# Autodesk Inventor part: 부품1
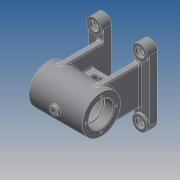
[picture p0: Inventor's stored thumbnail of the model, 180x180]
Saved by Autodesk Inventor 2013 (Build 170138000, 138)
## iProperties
Created: 2015-11
Part Number: 부품1
Material: 일반
Document SubType Name: Modeling
Designer: Administrator
Density: 1 g/cm^3
Author: Administrator
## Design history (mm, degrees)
sketch "스케치1"
  geometry: L1 (0, 0)-(70, 0); L2 (70, 0)-(70, 25); L3 (70, 25)-(0, 25); L4 (0, 25)-(0, 0); L5 (0, 16)-(12, 16); L6 (12, 16)-(12, 14); L7 (12, 14)-(14, 14); L8 (14, 14)-(14, 21); L9 (14, 21)-(56, 21); L10 (56, 21)-(56, 14); L11 (56, 14)-(58, 14); L12 (58, 14)-(58, 16); L13 (58, 16)-(70, 16)
  constraints: 26 end point, 8 parallel, 3 perpendicular, 2 collinear, 2 point on line, 1 horizontal
  dimensions: "d0" = 70 distance of L2.end L3.end; "d2" = 50 diameter of L3 L1; "d3" = 42 diameter of L9 L1; "d4" = 32 diameter of L13 L1; "d5" = 32 diameter of L5 L1; "d6" = 12 distance of L5.start L5.end; "d7" = 12 distance of L12.end L13.end; "d8" = 28 diameter of L7 L1; "d9" = 28 diameter of L11 L1; "d10" = 42 distance of L8.end L9.end
revolve "회전1" sketch "스케치1" stored, may be unused: angle "d11" = 90 deg
node "작업 평면1"
sketch "스케치2"
  geometry: L1 (-70, 25)-(-70, -25) reference; L2 (0, 25)-(0, -25) reference; L3 (-70, 25)-(-70, -25) reference; L4 (0, -25)-(-70, -25) reference; L5 (0, 25)-(-70, 25) reference; L6 (5, 40)-(5, -40); L7 (-35, 25)-(-35, -25); L8 (-5, 40)-(-5, -40); L9 (-15, 40)-(-15, -40); L10 (-55, 40)-(-55, -40); L11 (-75, 40)-(-75, -40); A1 r 10 centre (-5, 40) between (5, 40) and (-15, 40); A2 r 10 centre (-5, -40) between (-15, -40) and (5, -40); A3 r 10 centre (-65, -40) between (-75, -40) and (-55, -40); A4 r 10 centre (-65, 40) between (-55, 40) and (-75, 40); 1 further point
  constraints: 12 end point, 8 point on circle, 6 symmetric about line, 4 centre point, 2 coincident, 2 midpoint, 2 parallel, 2 tangent, 1 perpendicular, 2 other
  dimensions: "d13" = 80 distance of L6.start L6.end; "d16" = 40 vertical distance of L6.end point (0, 0); "d18" = 40 distance between parallel lines of L7 L6; "d19" = 20 distance between parallel lines of L9 L6; "d20" = 10 distance between parallel lines of L8 L6
extrude "돌출1" join sketch "스케치2" distance "d21" = 10; taper "d22" = 0 deg
sketch "스케치3"
  geometry: L1 (55, 40)-(55, -40) reference; L2 (75, -40)-(75, 40) reference; C1 r 10 at (65, -40); C2 r 10 at (5, -40); A1 r 10 centre (5, -40) between (-5, -40) and (15, -40) reference; A2 r 10 centre (5, 40) between (15, 40) and (-5, 40) reference; A3 r 10 centre (65, 40) between (75, 40) and (55, 40) reference; A4 r 10 centre (65, -40) between (55, -40) and (75, -40) reference; 3 further points
  constraints: 4 coincident, 2 centre point, 2 concentric, 2 horizontal alignment, 4 other
extrude "돌출2" join sketch "스케치3" distance "d23" = 3; taper "d24" = 0 deg
sketch "스케치4"
  geometry: L1 (80, 0)-(80, -10) reference; L2 (80, -10)-(80, -13) reference; L3 (0, 0)-(80, 0) reference; L4 (0, 0)-(0, -10) reference; L5 (80, -10)-(0, -10) reference; L6 (0, -10)-(0, -13) reference; L7 (65, -68)-(65, -10); L8 (0, -10)-(80, -10) reference; L9 (15, -68)-(15, -10); L10 (65, -10)-(15, -10); C1 r 21 at (40, -68) reference; A1 r 25 centre (40, -68) between (65, -68) and (15, -68) reference; A2 r 25 centre (40, -68) between (65, -68) and (15, -68); 1 further point
  constraints: 6 end point, 4 point on circle, 2 point on line, 2 tangent, 1 centre point, 1 coincident, 1 collinear, 1 concentric, 1 parallel, 1 perpendicular
extrude "돌출3" join sketch "스케치4" distance "d25" = 8; taper "d26" = 0 deg
sketch "스케치5"
  geometry: L1 (80, -10)-(0, -10) reference; L2 (0, 0)-(0, -10) reference; L3 (0, -10)-(0, -13) reference; L4 (0, 0)-(80, 0) reference; L5 (80, 0)-(80, -10) reference; L6 (80, -10)-(0, -10) reference; L7 (80, -10)-(80, -13) reference; L8 (65, -68)-(65, -10); L9 (15, -68)-(15, -10); L10 (65, -10)-(15, -10); C1 r 21 at (40, -68) reference; A1 r 25 centre (40, -68) between (65, -68) and (15, -68) reference; A2 r 25 centre (40, -68) between (65, -68) and (15, -68) reference; A3 r 25 centre (40, -68) between (65, -68) and (15, -68); 1 further point
  constraints: 6 end point, 6 point on circle, 2 point on line, 2 tangent, 1 centre point, 1 coincident, 1 collinear, 1 parallel, 1 perpendicular
extrude "돌출4" join sketch "스케치5" distance "d27" = 8; taper "d28" = 0 deg
sketch "스케치6"
  geometry: L1 (0, 25)-(7, 25) reference; L2 (7, 25)-(7, 58) reference; L3 (7, 58)-(-5, 58) reference; L4 (-5, 58)-(-5, 68) reference; L5 (-5, 68)-(15, 68) reference; L6 (15, 68)-(15, 25) reference; L7 (15, 25)-(55, 25) reference; L8 (55, 25)-(55, 68) reference; L9 (55, 68)-(75, 68) reference; L10 (75, 68)-(75, 58) reference; L11 (75, 58)-(63, 58) reference; L12 (63, 58)-(63, 25) reference; L13 (63, 25)-(70, 25) reference; L14 (70, 25)-(70, 16) reference; L15 (70, 16)-(58, 16) reference; L16 (58, 16)-(58, 14) reference; L17 (58, 14)-(56, 14) reference; L18 (56, 14)-(56, 21) reference; L19 (56, 21)-(14, 21) reference; L20 (14, 21)-(14, 14) reference; L21 (14, 14)-(12, 14) reference; L22 (12, 14)-(12, 16) reference; L23 (12, 16)-(0, 16) reference; L24 (0, 16)-(0, 25) reference; L25 (70, -25)-(0, -25) reference; L26 (0, -25)-(0, -16) reference; L27 (0, -16)-(12, -16) reference; L28 (12, -16)-(12, -14) reference; L29 (12, -14)-(14, -14) reference; L30 (14, -14)-(14, -21) reference; L31 (14, -21)-(56, -21) reference; L32 (56, -21)-(56, -14) reference; L33 (56, -14)-(58, -14) reference; L34 (58, -14)-(58, -16) reference; L35 (58, -16)-(70, -16) reference; L36 (70, -16)-(70, -25) reference; L37 (15, 45)-(55, 45); 1 further point
  constraints: 2 end point, 2 point on line, 1 perpendicular
  dimensions: "d29" = 20 distance between parallel lines of L37 L7
feature "리브1" sketch "스케치6" dims "d30" = 1, "d31" = 8, "d32" = 0, "d33" = 0, "d34" = 1, "d35" = 1
sketch "스케치7"
  geometry: L1 (40, -20.322)-(0, -20.322) reference; L2 (28, -13.5)-(12, -13.5); L3 (28, -6.5)-(12, -6.5); L4 (40, 23)-(60, 23) reference; L5 (-15, -70)-(55, -70) reference; L6 (40, -20.322)-(0, -20.322); L7 (20, -20.322)-(20, -16.631); A1 r 3.5 centre (28, -10) between (28, -13.5) and (28, -6.5); A2 r 3.5 centre (12, -10) between (12, -6.5) and (12, -13.5); 1 further point
  constraints: 8 end point, 4 point on circle, 3 tangent, 2 centre point, 2 equal length, 1 horizontal alignment, 1 midpoint, 1 perpendicular
  dimensions: "d36" = 7 diameter of A1; "d38" = 23 dimension on A2 A1; "d39" = 7 diameter of A2; "d40" = 33 vertical distance of A1.centre L4.start; "d41" = 11.5 dimension on A1 L7
extrude "돌출5" cut sketch "스케치7" stored distance "d42" = 8; taper "d43" = 0 deg
node "작업 평면2"
sketch "스케치8"
  geometry: C1 r 5 at (35, 0); 1 further point
  constraints: 1 centre point, 1 horizontal alignment
  dimensions: "d45" = 35 distance of C1.centre point (0, 0); "d46" = 10 diameter of C1
extrude "돌출6" join sketch "스케치8" stored distance "d47" = 8; taper "d48" = 0 deg
fillet "모깎기1" dims "d49" = 3
fillet "모깎기2" dims "d50" = 2
fillet "모깎기3" dims "d51" = 2
sketch "스케치9"
  geometry: C1 r 25 at (0, 0) reference; 1 further point
  constraints: 1 vertical alignment
  dimensions: "d52" = 20 distance of C1.centre point (0, 20)
hole "구멍1" sketch "스케치9" at (0, 20) diameter "d53" = 3.242; stored, may be unused: countersink angle "d57" = 90 deg, drill point angle "d59" = 118 deg; dims "d54" = 8, "d55" = 4, "d56" = 2, "d58" = 10
sketch "스케치10"
  geometry: C1 r 16 at (0, 0) reference; 1 further point
  constraints: 1 vertical alignment
  dimensions: "d60" = 20 distance of C1.centre point (0, 20)
hole "구멍2" sketch "스케치10" at (0, 20) diameter "d61" = 3.242; stored, may be unused: countersink angle "d65" = 90 deg, drill point angle "d67" = 118 deg; dims "d62" = 8, "d63" = 4, "d64" = 2, "d66" = 10
node "작업 평면3"
sketch "스케치11"
  geometry: 2 further points
  constraints: 1 horizontal alignment, 1 other
  dimensions: "d74" = 35 distance of point (0, 0) point (35, 0)
feature "엠보싱1" sketch "스케치11" dims "d0" = 70, "d2" = 50, "d3" = 42, "d4" = 32, "d5" = 32, "d6" = 12, "d7" = 12, "d8" = 28, "d9" = 28, "d10" = 42, "d75" = 0.5, "d76" = 0
fillet "모깎기4" dims "d77" = 0.3
chamfer "모따기1" distance "d78" = 1; stored, may be unused: second distance "d79" = 2, angle "d80" = 45 deg
sketch "스케치12"
  geometry: C1 r 10 at (0, 0) reference; C2 r 10 at (0, 80) reference; C3 r 10 at (60, 80) reference; C4 r 10 at (60, 0) reference; 1 further point
hole "구멍3" sketch "스케치12" at (0, 0), (0, 80), (60, 0), (60, 80) diameter "d81" = 6; stored, may be unused: countersink angle "d85" = 90 deg, drill point angle "d87" = 118 deg; dims "d82" = 6, "d83" = 12, "d84" = 4, "d86" = 10
chamfer "모따기2" distance "d88" = 1; stored, may be unused: second distance "d89" = 2, angle "d90" = 45 deg
fillet "모깎기5" dims "d91" = 0.3
hole "구멍4" diameter "d94" = 5.188; stored, may be unused: countersink angle "d98" = 90 deg, drill point angle "d100" = 118 deg; dims "d92" = 10, "d93" = 10, "d95" = 6, "d96" = 12, "d97" = 4, "d99" = 24.5
node "솔리드1"
pattern_circular "원형 패턴1" dims angle "d69" = 360 deg
pattern_circular "원형 패턴2" dims angle "d72" = 360 deg
node "투영된 루프1"
node "투영된 루프2"
node "투영된 루프3"
node "투영된 루프4"
node "절단 모서리 투영1"
node "절단 모서리 투영2"
node "절단 모서리 투영3"
other parameters: "d12" = 68, "d44" = -96
